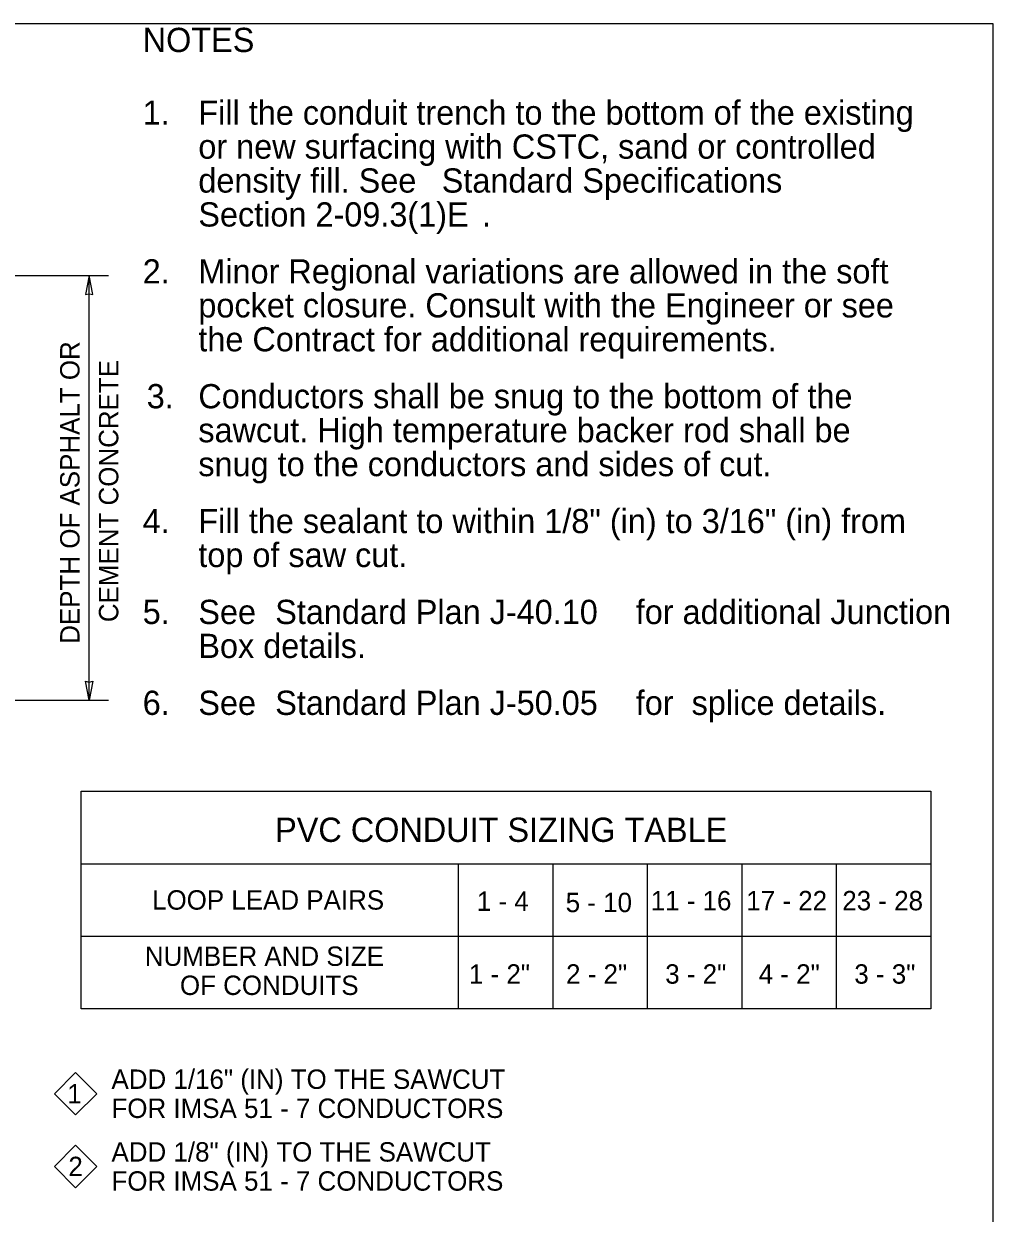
# Model space of a CAD drawing. Extents: x 99862 to 103151, y 100000 to 108153.
# Drawn here: x 102351 to 103151, y 101094 to 102076 of the extents above; entities that cross this region are included whole.
import ezdxf

# ---------------------------------------------------------------- set-up
doc = ezdxf.new("R2010")
doc.units = 0
for name, color, linetype in [('Level 1', 7, 'Continuous'), ('Level 15', 7, 'Continuous'), ('Level 18', 7, 'Continuous'), ('Level 20', 7, 'Continuous'), ('Level 60', 7, 'Continuous')]:
    doc.layers.add(name, color=color, linetype=linetype)

msp = doc.modelspace()

# ---------------------------------------------------------------- linework, layer by layer
at = {"layer": 'Level 1'}
for p, q in [((102398.61, 101262.69), (102398.61, 101442.32)), ((102398.61, 101442.32), (103099.57, 101442.32)), ((103099.57, 101442.26), (103099.57, 101262.63)), ((102398.61, 101382.32), (103099.57, 101382.32)), ((102709.57, 101382.26), (102709.57, 101262.63)), ((102787.57, 101382.26), (102787.57, 101262.63)), ((102865.57, 101382.26), (102865.57, 101262.63)), ((102943.57, 101382.26), (102943.57, 101262.63)), ((103021.57, 101382.26), (103021.57, 101262.63)), ((102398.61, 101322.54), (103099.57, 101322.54)), ((103099.57, 101262.69), (102398.61, 101262.69))]:
    msp.add_line(p, q, dxfattribs=at)
msp.add_lwpolyline([(99862, 99999.5), (103151, 99999.5), (103151, 102075.5), (99862, 102075.5)], close=True, dxfattribs=at)
at = {"layer": 'Level 15'}
for points in [[(102255.17, 101867.78), (102421.17, 101867.78)], [(102405.17, 101517.27), (102405.17, 101867.78)], [(102265.1, 101517.27), (102421.17, 101517.27)]]:
    msp.add_lwpolyline(points, dxfattribs=at)
for points in [[(102405.17, 101867.78), (102402.08, 101852.06), (102405.17, 101852.78), (102408.25, 101852.06)], [(102405.17, 101517.27), (102402.08, 101532.99), (102405.17, 101532.27), (102408.25, 101532.99)]]:
    msp.add_lwpolyline(points, close=True, dxfattribs=at)
at = {"layer": 'Level 20'}
for points in [[(102393.96, 101210.15), (102411.52, 101192.6), (102393.96, 101175.05), (102376.41, 101192.6)], [(102393.96, 101150.15), (102411.52, 101132.6), (102393.96, 101115.05), (102376.41, 101132.6)]]:
    msp.add_lwpolyline(points, close=True, dxfattribs=at)
at = {"layer": 'Level 60'}
msp.add_line((103151, 102075.5), (103151, 102075.5), dxfattribs=at)

# ---------------------------------------------------------------- texts
at = {"layer": 'Level 18'}
for s, p in [('DEPTH OF ASPHALT OR', (102397.17, 101563.89)), ('CEMENT CONCRETE', (102429.17, 101581.73))]:
    msp.add_text(s, height=16, rotation=90, dxfattribs=at).set_placement(p)
for s, p in [('ADD 1/16" (IN) TO THE SAWCUT ', (102423.52, 101196.6)), ('FOR IMSA 51 - 7 CONDUCTORS', (102423.52, 101172.6)), ('ADD 1/8" (IN) TO THE SAWCUT ', (102423.52, 101136.6)), ('FOR IMSA 51 - 7 CONDUCTORS', (102423.52, 101112.6))]:
    msp.add_text(s, height=16, dxfattribs=at).set_placement(p)
at = {"layer": 'Level 20'}
for s, height, p in [('NOTES', 20, (102449.29, 102052.19)), ('1.', 20, (102449.29, 101992.19)), ('Fill the conduit trench to the bottom of the existing', 20, (102495.2, 101992.19)), ('or new surfacing with CSTC, sand or controlled ', 20, (102495.2, 101964.19)), ('density fill. See ', 20, (102495.2, 101936.19)), ('Standard Specifications ', 20, (102696.01, 101936.19)), ('Section 2-09.3(1)E', 20, (102495.2, 101908.19)), ('. ', 20, (102729.22, 101908.19)), ('2.', 20, (102449.29, 101861.19)), ('Minor Regional variations are allowed in the soft ', 20, (102495.2, 101861.19)), ('pocket closure. Consult with the Engineer or see ', 20, (102495.2, 101833.19)), ('the Contract for additional requirements.', 20, (102495.2, 101805.19)), ('3.', 20, (102452.6, 101758.19)), ('Conductors shall be snug to the bottom of the ', 20, (102495.2, 101758.19)), ('sawcut. High temperature backer rod shall be', 20, (102495.2, 101730.19)), ('snug to the conductors and sides of cut.', 20, (102495.2, 101702.19)), ('4.', 20, (102449.29, 101655.19)), ('Fill the sealant to within 1/8" (in) to 3/16" (in) from ', 20, (102495.2, 101655.19)), ('top of saw cut.', 20, (102495.2, 101627.19)), ('5.', 20, (102449.29, 101580.19)), ('See ', 20, (102495.2, 101580.19)), ('Standard Plan J-40.10 ', 20, (102558.64, 101580.19)), ('for additional Junction ', 20, (102856.1, 101580.19)), ('Box details.', 20, (102495.2, 101552.19)), ('Standard Plan J-50.05 ', 20, (102558.64, 101505.19)), ('for  splice details.', 20, (102856.1, 101505.19)), ('6.', 20, (102449.29, 101505.19)), ('See ', 20, (102495.2, 101505.19)), (' PVC CONDUIT SIZING TABLE ', 20, (102551.13, 101400.41)), ('LOOP LEAD PAIRS', 16, (102457.04, 101344.51)), ('1 - 4', 16, (102724.98, 101343.49)), ('11 - 16', 16, (102868.4, 101343.95)), ('17 - 22', 16, (102947.31, 101343.95)), ('23 - 28', 16, (103026.49, 101343.95)), ('5 - 10', 16, (102798.28, 101342.44)), ('NUMBER AND SIZE ', 16, (102451.03, 101298.09)), ('1 - 2"', 16, (102718.45, 101283.42)), ('2 - 2" ', 16, (102798.58, 101283.42)), ('3 - 2"', 16, (102880.4, 101283.42)), ('4 - 2"', 16, (102957.53, 101283.42)), ('3 - 3"', 16, (103036.4, 101283.42)), ('OF CONDUITS', 16, (102480.01, 101274.09)), ('1', 16, (102387.1, 101184.6)), ('2', 16, (102387.98, 101124.6))]:
    msp.add_text(s, height=height, dxfattribs=at).set_placement(p)

doc.saveas('drawing.dxf')
